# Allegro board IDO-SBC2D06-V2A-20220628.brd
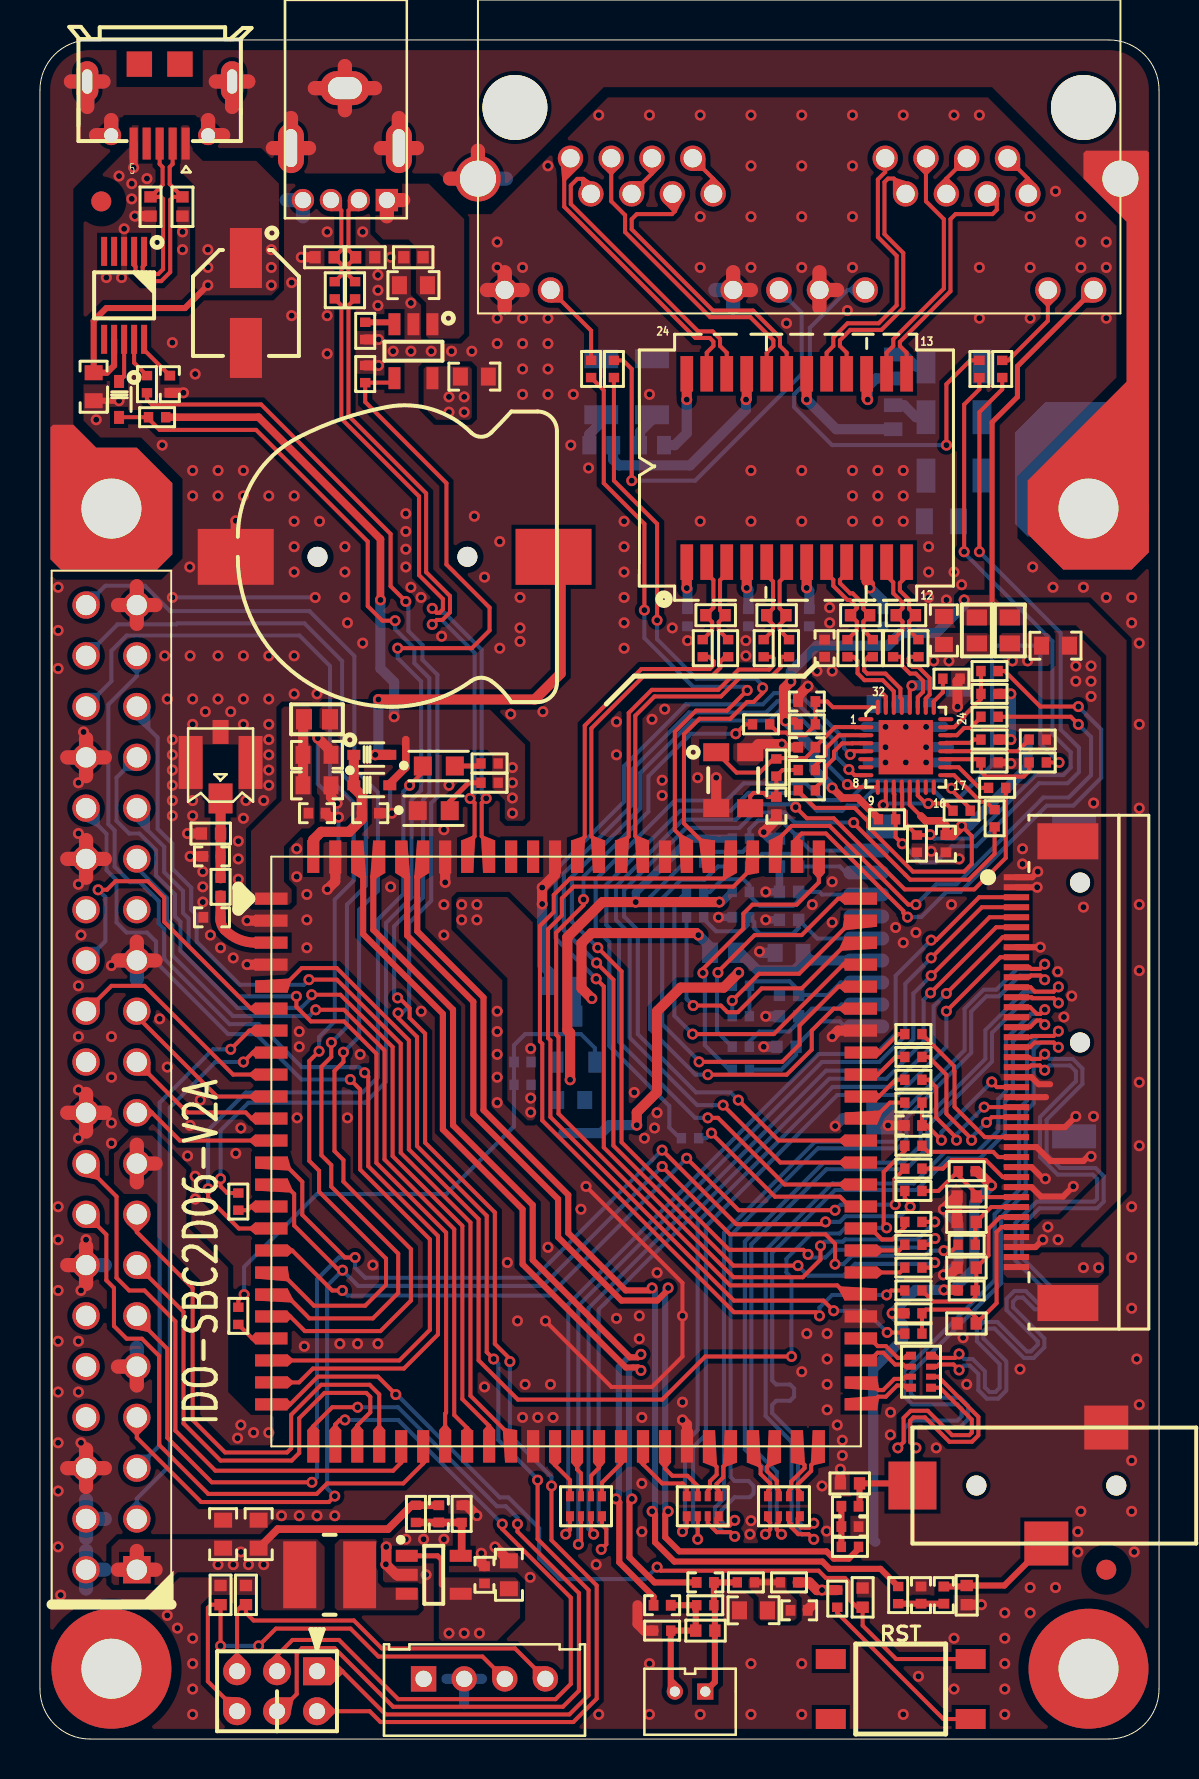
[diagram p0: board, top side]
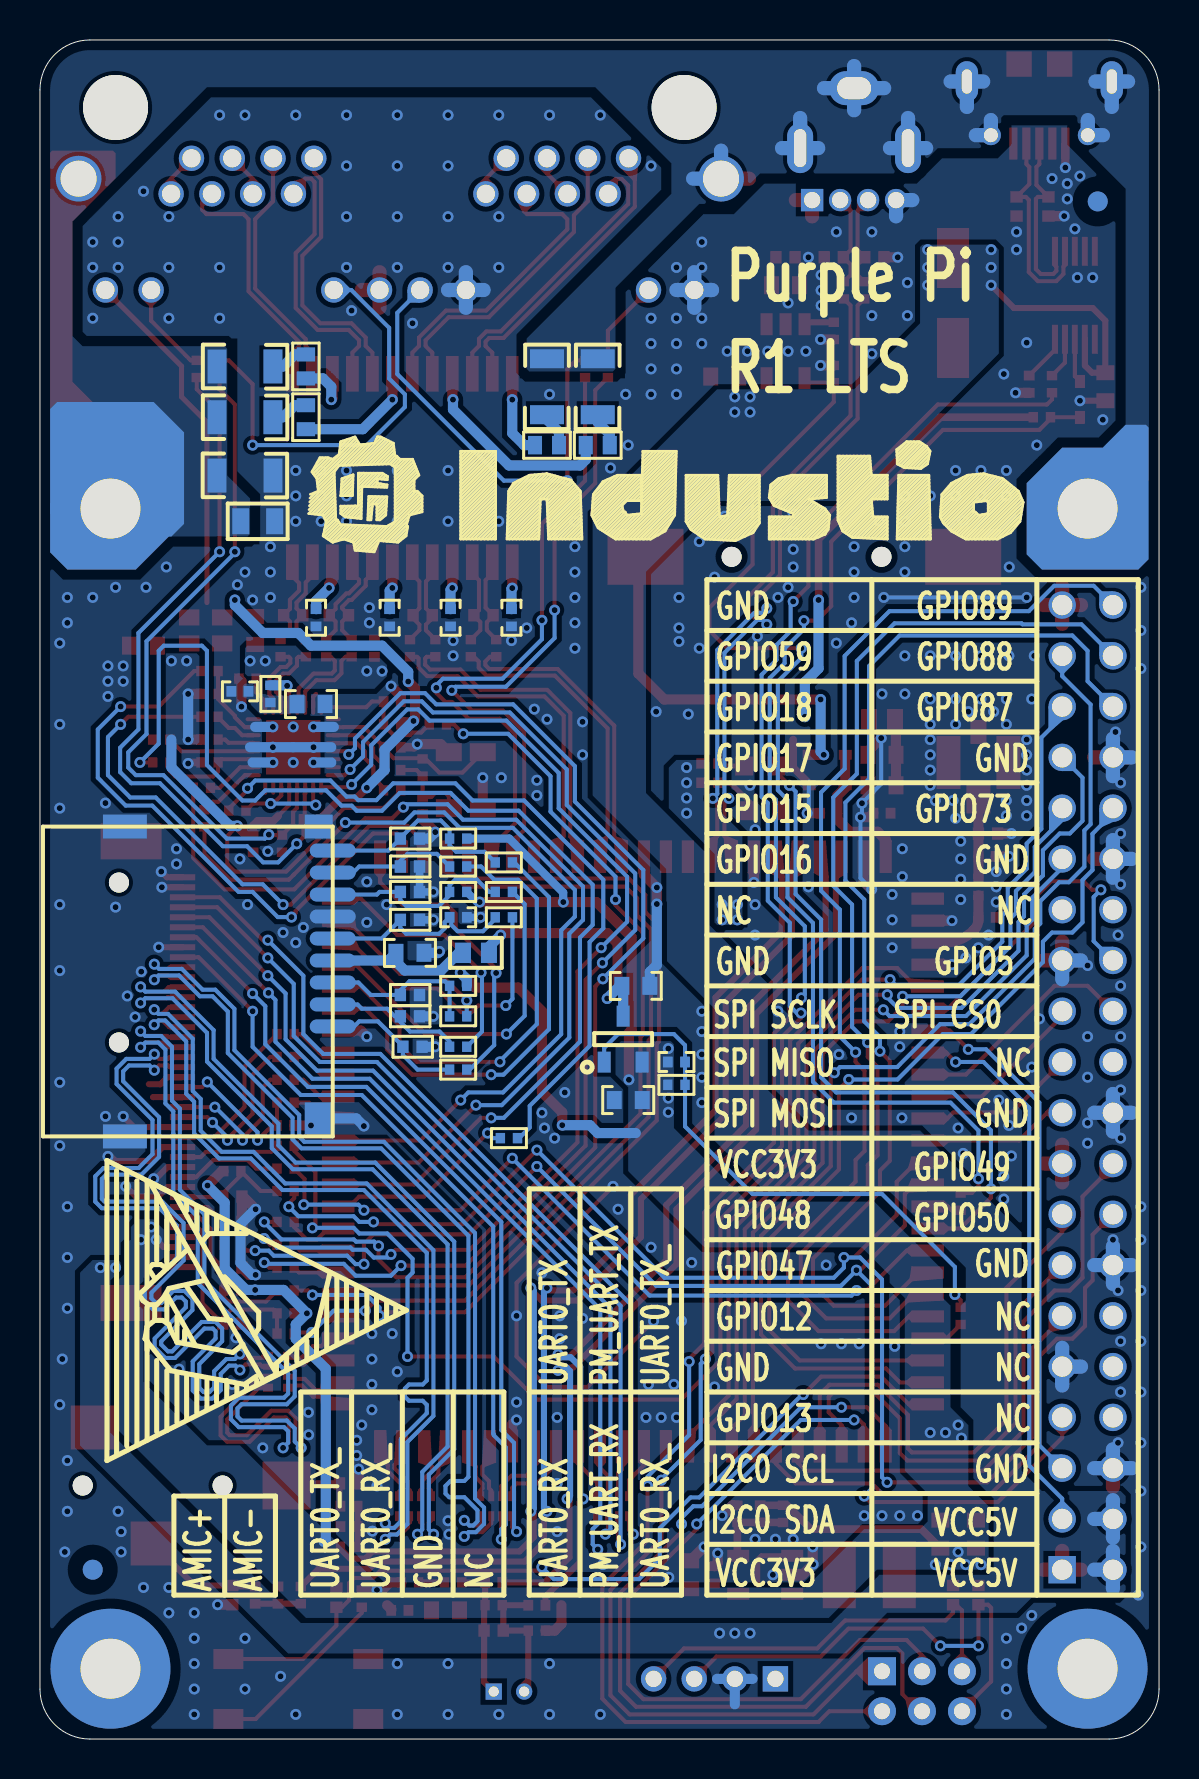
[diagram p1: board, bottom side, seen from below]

Outline 56 x 85 mm; copper layers: TOP, BOTTOM. Coordinates in mm from the lower left corner of the outline.
Outline path: 0,82.5 arc(0.73,84.27) 2.5,85 53.5,85 arc(55.27,84.27) 56,82.5 56,2.5 arc(55.27,0.73) 53.5,0 2.5,0 arc(0.73,0.73) 0,2.5 0,82.5

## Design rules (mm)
net group PANEL_DE: nets PANEL_DE TTL27/LCD_DE
net group PANEL_HS: nets PANEL_HS TTL25/LCD_HSYNC
net group PANEL_VS: nets PANEL_VS TTL26/LCD_VSYNC
net group CLK: nets 50MHZ_CLKOUT DMIC_CLK DMIC_L DMIC_R GPIO1/RMII_MDC PANEL_DCLK RMII_MDC RMII_REF_CLK TTL20 TTL24/LCD_PCLK
net group LAN: nets ETH_RN ETH_RP ETH_RXN ETH_RXP ETH_TN ETH_TP ETH_TXN ETH_TXP LAN0-R+ LAN0-R- LAN0-T+ LAN0-T- LAN1-R+ LAN1-R- LAN1-T+ LAN1-T- MDI_RN MDI_RP MDI_RXN MDI_RXP MDI_TN MDI_TP MDI_TXN MDI_TXP PANEL_B3 PANEL_B4 PANEL_B5 PANEL_B6 PANEL_B7 PANEL_G2 PANEL_G3 PANEL_G4 PANEL_G5 PANEL_G6 PANEL_G7 PANEL_R3 PANEL_R4 PANEL_R5 PANEL_R6 PANEL_R7 TTL0 TTL1 TTL2 TTL3 TTL4 TTL5 TTL6/MIPI_TX_D0P TTL7/MIPI_TX_D0N TTL8/MIPI_TX_D1P TTL9/MIPI_TX_D1N TTL10/MIPI_TX_CKP TTL11/MIPI_TX_CKN TTL12/MIPI_TX_D2P TTL13/MIPI_TX_D2N TTL14/MIPI_TX_D3P TTL15/MIPI_TX_D3N
net group PHY_DVDD33: nets RMII_MDIO
net group SD: nets SD_CDZ SD_CLK SD_CLK_ SD_CMD SD_CMD_ SD_D0 SD_D0_ SD_D1 SD_D1_ SD_D2 SD_D2_ SD_D3 SD_D3_
net group USB: nets DM_P1 DM_P2 DM_P2_ DP_P1 DP_P2 DP_P2_ UD+ UD-

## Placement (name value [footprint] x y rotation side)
C1  100uF/10V  [CAPAE530X540]  10.31 71.84 270 top
C2  10uF  [C0603L]  23.46 8.22 270 top
C3  1uF  [C0402L]  22.25 8.22 270 top
C4  6.8pF  [C0402L]  19.96 11.26 90 top
C5  22uF  [C0603L]  10.94 10.25 270 top
C6  22uF  [C0603L]  9.16 10.25 270 top
C7  1uF  [C0402L]  16.53 46.32 180 top
C8  100nF  [C0402L]  13.86 46.32 180 top
C9  22uF  [C0603L]  13.86 49.24 180 top
C10  22uF  [C0603L]  13.86 47.71 180 top
C11  NC/10pF  [C0402L]  8.61 41.11 0 top
C12  NC/10pF  [C0402L]  8.61 44.16 0 top
C13  10uF  [C0603L]  37.49 39.33 0 bottom
C14  NC/6.8pF  [C0402L]  35.07 41.11 0 bottom
C15  10uF  [C0603L]  26.56 31.97 180 bottom
C16  1uF  [C0402L]  24.15 33.87 0 bottom
C17  10uF  [C0603L]  26.18 37.68 0 bottom
C18  10uF  [C0603L]  18.69 72.73 0 top
C19  10uF  [C0603L]  21.74 68.16 180 top
C20  100nF  [C0402L]  32.41 56.1 270 bottom
C21  1nF  [C1206L]  30.63 67.65 270 bottom
C22  100nF  [C0402L]  35.45 56.1 270 bottom
C23  1nF  [C1206L]  28.09 67.65 270 bottom
C24  100nF  [C0402L]  38.5 56.1 270 bottom
C25  1nF  [C1206L]  45.74 66.13 180 bottom
C26  100nF  [C0402L]  42.18 56.1 270 bottom
C27  1nF  [C1206L]  45.74 68.67 180 bottom
C28  1nF  [C1206L]  45.74 63.21 0 bottom
C29  100nF  [C0402L]  45.99 52.41 180 bottom
C30  10uF  [C0603L]  42.44 51.78 0 bottom
C31  10uF  [C0603L]  50.82 54.7 180 top
C32  100nF  [C0402L]  45.33 44.79 90 top
C33  10uF  [C0603L]  45.23 55.46 270 top
C34  100nF  [C0402L]  39.26 54.57 270 top
C35  18pF  [C0402L]  38.37 49.62 0 top
C36  100nF  [C0402L]  38.37 51.9 0 top
C37  18pF  [C0402L]  36.85 46.7 90 top
C38  NC/6.8pF  [C0402L]  43.71 30.7 0 top
C39  4.7uF  [C0402L]  40.53 11.65 180 top
C40  4.7uF  [C0402L]  45.23 7.2 270 top
C41  NC/4.7uF  [C0402L]  44.09 7.2 270 top
C42  NC/4.7uF  [C0402L]  40.53 10.63 180 top
C43  10uF  [C0603L]  35.71 6.44 0 top
C44  100nF  [C0402L]  37.99 6.44 180 top
C45  1uF  [C0402L]  33.29 7.84 180 top
C46  1uF  [C0402L]  31.14 6.69 180 top
C47  10uF  [C0603L]  2.69 67.65 90 top
C48  100nF  [C0402L]  6.5 67.78 90 top
D1  ES0402V014CT  [V0402]  7.13 76.67 270 top
D2  ES0402V014CT  [V0402]  5.53 76.67 270 top
D3  ES0402V014CT  [V0402]  41.17 7.07 90 top
D4  LRB520S-30T1G  [SOD523]  16.61 47.71 0 top
D5  LRB520S-30T1G  [SOD523]  16.61 49.24 0 top
D6  ES0402V014CT  [V0402]  8.56 45.3 180 top
D7  ES0402V014CT  [V0402]  37.49 42.38 180 bottom
D8  ES0402V014CT  [V0402]  37.49 43.65 180 bottom
D9  ES0402V014CT  [V0402]  37.36 34.63 180 bottom
D10  ES0402V014CT  [V0402]  37.49 36.16 180 bottom
D11  ES0402V014CT  [V0402]  37.49 37.22 180 bottom
D12  ES0402V014CT  [V0402]  37.49 45.05 180 bottom
D13  ES0402V014CT  [V0402]  37.49 40.98 180 bottom
D14  ES0402V014CT  [V0402]  14.24 74.13 180 top
D15  ES0402V014CT  [V0402]  16.28 74.13 0 top
D16  ES0402V014CT  [V0402]  18.69 74.13 180 top
D17  ES0402V014CT  [V0402]  33.8 56.22 0 top
D18  ES0402V014CT  [V0402]  36.85 56.22 0 top
D19  ES0402V014CT  [V0402]  41.04 56.22 0 top
D20  ES0402V014CT  [V0402]  43.33 56.22 0 top
D21  ES0402V014CT  [V0402]  46.38 25.87 180 top
D22  ES0402V014CT  [V0402]  46.38 27.14 180 top
D23  ES0402V014CT  [V0402]  46.38 20.79 180 top
D24  ES0402V014CT  [V0402]  46.38 23.58 180 top
D25  ES0402V014CT  [V0402]  46.38 7.2 270 top
D26  ES0402V014CT  [V0402]  40.53 12.79 180 top
D27  NC/ES0402V014CT  [V0402]  33.29 5.42 0 top
D28  ES0402V014CT  [V0402]  10.31 7.2 90 top
D29  ES0402V014CT  [V0402]  9.04 7.2 90 top
D30  LRB520S-30T1G  [SOD523]  3.96 67.02 270 top
H1  HOLE  [MTG300_600]  52.47 3.52 0 top
H2  HOLE  [MTG300_600]  52.47 61.56 0 top
H3  HOLE  [MTG300_600]  3.58 61.56 0 top
H4  HOLE  [MTG300_600]  3.58 3.52 0 top
J1  MicroUSB  [MICROUSB-5SB]  5.99 79.72 0 top
J2  -  [CR1220-2P-SMD]  9.8 59.14 0 top
J3  IPEX  [IPEX-20279-001E]  9.04 48.86 270 top
J4  SD  [TF-01A]  41.55 35.65 270 bottom
J5  USB-4AF  [USB-4AF-DIP-3W]  15.26 79.59 180 top
J6  RJ45  [RJ45-1X2-8P8C-R-LED]  45.87 81.62 180 top
J7  -  [FPC05-PDW-40P]  50.44 33.36 90 top
J8  PJ-326-3P  [PJ-326A-3P]  53.36 15.58 180 top
J9  MX1.25T-2A  [MX125T-2A]  33.29 2.37 0 top
J10  PH2.0-4A  [PH200-4A]  25.29 3.01 180 top
J11  -  [HDR200MA-2X3]  13.86 3.39 180 top
J12  -  [HDR254MA-2X20]  4.08 31.33 180 top
L1  2.2uH/4.3A  [L4040]  14.5 8.22 180 top
L2  UPZ1608E101-3R0TF  [L0603]  13.86 51.02 180 top
L3  UPZ1608E101-3R0TF  [L0603]  34.18 39.33 0 bottom
L4  UPZ1608E101-3R0TF  [L0603]  48.53 55.46 270 top
L5  UPZ1608E101-3R0TF  [L0603]  46.88 55.46 270 top
LED1  Blue LED0603  [LED0603]  19.96 48.68 0 top
LED2  Blue LED0603  [LED0603]  19.71 46.44 0 top
MARK1  FID10X20  [MARK]  53.36 8.47 0 top
MARK2  FID10X20  [MARK]  3.07 76.92 180 bottom
MARK3  FID10X20  [MARK]  53.36 8.47 180 bottom
MARK4  FID10X20  [MARK]  3.07 76.92 0 top
Q1  CJ3401  [SOT23]  26.82 35.01 90 bottom
R1  4.7K  [R0402L]  39.9 7.02 270 top
R2  1K  [R0402L]  22.5 48.81 180 top
R3  200K  [R0402L]  18.82 11.26 270 top
R4  1K  [R0402L]  22.5 47.84 180 top
R5  44.2K  [R0402L]  21.1 11.26 90 top
R6  0R  [R0402L]  9.04 42.63 90 top
R7  10K  [R0402L]  35.07 42.38 0 bottom
R8  10K  [R0402L]  35.07 37.68 0 bottom
R9  10K  [R0402L]  35.07 45.05 0 bottom
R10  22R  [R0402L]  32.79 42.38 0 bottom
R11  22R  [R0402L]  35.07 43.65 0 bottom
R12  0R  [R0402L]  15.77 72.48 90 top
R13  22R  [R0402L]  35.07 33.49 0 bottom
R14  0R  [R0402L]  14.75 72.48 90 top
R15  22R  [R0402L]  35.07 34.63 0 bottom
R16  22R  [R0402L]  35.07 36.16 0 bottom
R17  22R  [R0402L]  32.79 43.85 0 bottom
R18  22R  [R0402L]  32.79 41.11 0 bottom
R19  22R  [R0402L]  9.93 26.89 90 top
R20  100K  [R0402L]  24.15 32.73 180 bottom
R21  10K  [R0402L]  9.93 21.17 90 top
R22  6.8K  [R0402L]  16.28 70.45 270 top
R23  2.2R  [R0402L]  33.17 54.57 90 top
R24  75R  [R0603L]  30.63 64.73 180 bottom
R25  2.2R  [R0402L]  34.44 54.57 90 top
R26  2.2R  [R0402L]  36.22 54.57 90 top
R27  2.2R  [R0402L]  37.49 54.57 90 top
R28  75R  [R0603L]  28.09 64.73 180 bottom
R29  1K  [R0402L]  27.58 68.54 90 top
R30  2.2R  [R0402L]  40.41 54.57 90 top
R31  1K  [R0402L]  28.72 68.54 90 top
R32  75R  [R0603L]  42.69 66.13 90 bottom
R33  2.2R  [R0402L]  41.68 54.57 90 top
R34  2.2R  [R0402L]  42.69 54.57 90 top
R35  75R  [R0603L]  42.69 68.67 90 bottom
R36  1K  [R0402L]  47.01 68.54 270 top
R37  2.2R  [R0402L]  43.96 54.57 90 top
R38  1K  [R0402L]  48.15 68.54 270 top
R39  1M  [R0805L]  45.11 60.92 0 bottom
R40  22R  [R0402L]  47.52 53.43 180 top
R41  22R  [R0402L]  47.52 51.14 180 top
R42  0R  [R0402L]  44.47 52.29 270 bottom
R43  22R  [R0402L]  49.93 48.86 180 top
R44  22R  [R0402L]  47.9 47.59 180 top
R45  22R  [R0402L]  47.77 46.06 90 top
R46  6.19K  [R0402L]  45.61 53.05 0 top
R47  22R  [R0402L]  32.53 30.06 180 bottom
R48  22R  [R0402L]  43.71 24.73 0 top
R49  22R  [R0402L]  43.71 23.58 0 top
R50  22R  [R0402L]  43.71 25.87 0 top
R51  22R  [R0402L]  36.09 50.76 0 top
R52  0R  [R0402L]  46.12 46.44 180 top
R53  1M  [R0402L]  36.85 48.6 270 top
R54  0R  [R0402L]  38.37 48.48 0 top
R55  4.7K  [R0402L]  38.37 47.46 0 top
R56  4.7K  [R0402L]  49.93 50 180 top
R57  470K  [R0402L]  38.37 50.76 0 top
R58  4.7K  [R0402L]  47.52 48.86 180 top
R59  4.7K  [R0402L]  47.52 50 180 top
R60  4.7K  [R0402L]  47.52 52.29 180 top
R61  4.7K  [R0402L]  42.39 46.01 0 top
R62  4.7K  [R0402L]  43.89 44.79 270 top
R63  22R  [RN_0402X4]  27.33 11.65 270 top
R64  22R  [RN_0402X4]  37.23 11.65 270 top
R65  22R  [RN_0402X4]  33.17 11.65 270 top
R66  22R  [RN_0402X4]  44.09 18.38 0 top
R67  22R  [R0402L]  43.71 32.98 0 top
R68  22R  [R0402L]  43.71 34.12 0 top
R69  22R  [R0402L]  43.71 35.27 0 top
R70  22R  [R0402L]  43.71 29.68 0 top
R71  22R  [R0402L]  43.71 28.54 0 top
R72  22R  [R0402L]  43.71 31.84 0 top
R73  NC/4.7K  [R0402L]  46.38 28.41 180 top
R74  4.7K  [R0402L]  43.71 21.3 0 top
R75  4.7K  [R0402L]  46.38 22.44 0 top
R76  22R  [R0402L]  43.71 22.44 0 top
R77  22R  [R0402L]  43.71 20.28 0 top
R78  22R  [R0402L]  46.38 24.73 0 top
R79  22R  [R0402L]  43.71 27.42 0 top
R80  0R  [R0402L]  40.53 9.61 180 top
R81  0R  [R0402L]  42.95 7.2 270 top
R82  4.7K  [R0402L]  37.49 7.84 180 top
R83  2K  [R0402L]  35.33 7.84 180 top
R84  NC/2K  [R0402L]  33.29 6.69 180 top
R85  2K  [R0402L]  31.14 5.42 180 top
R88  22R  [R0402L]  5.35 67.78 90 top
R89  10K  [R0402L]  5.86 66.13 180 top
R123  510K  [R0402L]  16.28 68.29 90 top
SW1  T-switch  [PB-4P-S-4_5X4_5]  43.07 2.5 180 top
U1  TLV62569DBVR  [SOT23-5]  19.71 8.22 0 top
U2  U-2D01  [IDO_2D01_LGA96]  11.58 43.14 0 top
U3  SY6280AAC  [SOT23-5]  18.69 69.43 270 top
U4  QT24A01  [QT24A01-SOP24]  37.87 63.59 270 top
U5  IP101GR  [IP101GR-VQFN-32]  43.33 49.62 0 top
U6  CH340E  [MSOP-10]  4.21 72.22 270 top
XT1  25MHz  [XTAL_32X25_4P]  34.69 47.97 0 top

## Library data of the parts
C1 = C-AL-SMD
C2 C5 C6 C9 C10 C13 C15 C17-C19 C30 C31 C33 C43 C47 = C-0603
C3 C4 C7 C8 C11 C12 C14 C16 C20 C22 C24 C26 C29 C32 C34-C42 C44-C46 C48 = C-0402
C21 C23 C25 C27 C28 = C-1206
D1-D3 D6-D29 = DI-ESD
D4 D5 D30 = DI-XI-S
H1-H4 = HOLE: User Part Number: pn; Tolerance: RichardLC
J1 = J-MicroUSB_0
J2 = RTC-CR1220-2P-SMD
J3 = RF-IPEX-20279
J4 = J-TF-01A
J5 = J-USB-4AF-DIP-W-3_1
J6 = J-RJ45-1X2
J7 = J-FPC05-40P: User Part Number: DENG
J8 = J-PJ-326A-3P
J9 = J-H-2P
J10 = J-H-4P
J11 = J-HDR-D-6: User Part Number: pn; Tolerance: RichardLC
J12 = J-HDR-D-40
L1 = L-IND
L2 L4 L5 = FB-0603
L3 = FB-0603: signal model: CM-LITE_0_CMLS-ACM2012_ACM201_1_ACM2012-900-2P_NC
LED1 LED2 = D-LED0603
MARK1-MARK4 = MTG240_600_NPH_0
Q1 = P-MOS
R1-R23 R25-R27 R29-R31 R33 R34 R36-R38 R40-R59 R70-R85 R88 R89 R123 = R-0402
R24 R28 R32 R35 = R-0603
R39 = R-0805
R60-R62 = R-0402: signal model: R_R0402_33R_33R
R63-R66 = RN_0402X4
R67-R69 = R-0402: signal model: R_R0402_10K_10K
SW1 = SW-TS4550TP
U1 = U-TLV62569DBVR
U2 = U-2D01_1
U3 = U-SY6280AAC
U4 = U-QT24A01_0
U5 = U-IP101GR
U6 = U-CH340E_0
XT1 = XTAL-4P

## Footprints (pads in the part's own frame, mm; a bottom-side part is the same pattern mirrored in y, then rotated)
C0402L
  rect 0.49x0.54 smd: 1(-0.43,0) 2(0.43,0)
C0603L
  rect 0.75x0.9 smd: 1(-0.7,0) 2(0.7,0)
C1206L
  rect 0.95x1.7 smd: 1(-1.4,0) 2(1.4,0)
CAPAE530X540
  rect 3x1.6 smd: 1(-2.25,0) 2(2.25,0)
CR1220-2P-SMD
  round 1.001 hole 1.199 unplated: (4.089,0) (11.59,0)
  rect 3.8x2.799 smd: 1(15.9,0) 2(0,0)
FPC05-PDW-40P
  rect 0.305x1.27 smd: 1(9.751,1.575) 2(9.251,1.575) 3(8.75,1.575) 4(8.25,1.575) 5(7.749,1.575) 6(7.249,1.575) 7(6.749,1.575) 8(6.251,1.575) 9(5.751,1.575) 10(5.25,1.575) 11(4.75,1.575) 12(4.249,1.575) 13(3.749,1.575) 14(3.251,1.575) 15(2.751,1.575) 16(2.25,1.575) 17(1.75,1.575) 18(1.25,1.575) 19(0.749,1.575) 20(0.249,1.575) 21(-0.249,1.575) 22(-0.749,1.575) 23(-1.25,1.575) 24(-1.75,1.575) 25(-2.25,1.575) 26(-2.751,1.575) 27(-3.251,1.575) 28(-3.749,1.575) 29(-4.249,1.575) 30(-4.75,1.575) 31(-5.25,1.575) 32(-5.751,1.575) 33(-6.251,1.575) 34(-6.749,1.575) 35(-7.249,1.575) 36(-7.749,1.575) 37(-8.25,1.575) 38(-8.75,1.575) 39(-9.251,1.575) 40(-9.751,1.575)
  rect 1.803x3.048 smd: 41(11.549,-1.001) 42(-11.549,-1.001)
HDR200MA-2X3
  rect 1.4x1.4 hole 0.8: 1(0,0)
  round 1.4 hole 0.8: 2(0,2) 3(2,0) 4(2,2) 5(4,0) 6(4,2)
HDR254MA-2X20
  rect 1.372x1.372 hole 1.016: 1(-0.762,22.86)
  round 1.372 hole 1.016: 2(1.778,22.86) 3(-0.762,20.32) 4(1.778,20.32) 5(-0.762,17.78) 6(1.778,17.78) 7(-0.762,15.24) 8(1.778,15.24) 9(-0.762,12.7) 10(1.778,12.7) 11(-0.762,10.16) 12(1.778,10.16) 13(-0.762,7.62) 14(1.778,7.62) 15(-0.762,5.08) 16(1.778,5.08) 17(-0.762,2.54) 18(1.778,2.54) 19(-0.762,0) 20(1.778,0) 21(-0.762,-2.54) 22(1.778,-2.54) 23(-0.762,-5.08) 24(1.778,-5.08) 25(-0.762,-7.62) 26(1.778,-7.62) 27(-0.762,-10.16) 28(1.778,-10.16) 29(-0.762,-12.7) 30(1.778,-12.7) 31(-0.762,-15.24) 32(1.778,-15.24) 33(-0.762,-17.78) 34(1.778,-17.78) 35(-0.762,-20.32) 36(1.778,-20.32) 37(-0.762,-22.86) 38(1.778,-22.86) 39(-0.762,-25.4) 40(1.778,-25.4)
IDO_2D01_LGA96
  rect 1.626x0.61 smd: 1(0,-1.1) 2(0,-2.2) 3(0,-3.3) 4(0,-4.4) 5(0,-5.5) 6(0,-6.6) 7(0,-7.7) 8(0,-8.8) 9(0,-9.9) 10(0,-11) 11(0,-12.1) 12(0,-13.2) 13(0,-14.3) 14(0,-15.4) 15(0,-16.5) 16(0,-17.6) 17(0,-18.7) 18(0,-19.8) 19(0,-20.9) 20(0,-22) 21(0,-23.1) 22(0,-24.2) 23(0,-25.3) 24(0,-26.4) 49(29.5,-26.4) 50(29.5,-25.3) 51(29.5,-24.2) 52(29.5,-23.1) 53(29.5,-22) 54(29.5,-20.9) 55(29.5,-19.8) 56(29.5,-18.7) 57(29.5,-17.6) 58(29.5,-16.5) 59(29.5,-15.4) 60(29.5,-14.3) 61(29.5,-13.2) 62(29.5,-12.1) 63(29.5,-11) 64(29.5,-9.9) 65(29.5,-8.8) 66(29.5,-7.7) 67(29.5,-6.6) 68(29.5,-5.5) 69(29.5,-4.4) 70(29.5,-3.3) 71(29.5,-2.2) 72(29.5,-1.1)
  rect 0.61x1.626 smd: 25(2.1,-28.5) 26(3.2,-28.5) 27(4.3,-28.5) 28(5.4,-28.5) 29(6.5,-28.5) 30(7.6,-28.5) 31(8.7,-28.5) 32(9.8,-28.5) 33(10.9,-28.5) 34(12,-28.5) 35(13.1,-28.5) 36(14.2,-28.5) 37(15.3,-28.5) 38(16.4,-28.5) 39(17.5,-28.5) 40(18.6,-28.5) 41(19.7,-28.5) 42(20.8,-28.5) 43(21.9,-28.5) 44(23,-28.5) 45(24.1,-28.5) 46(25.2,-28.5) 47(26.3,-28.5) 48(27.4,-28.5) 73(27.4,1) 74(26.3,1) 75(25.2,1) 76(24.1,1) 77(23,1) 78(21.9,1) 79(20.8,1) 80(19.7,1) 81(18.6,1) 82(17.5,1) 83(16.4,1) 84(15.3,1) 85(14.2,1) 86(13.1,1) 87(12,1) 88(10.9,1) 89(9.8,1) 90(8.7,1) 91(7.6,1) 92(6.5,1) 93(5.4,1) 94(4.3,1) 95(3.2,1) 96(2.1,1)
IP101GR-VQFN-32
  oval 0.762x0.203 smd: 1(-2,1.4) 2(-2,1) 3(-2,0.6) 4(-2,0.2) 5(-2,-0.2) 6(-2,-0.6) 7(-2,-1) 8(-2,-1.4) 17(2,-1.4) 18(2,-1) 19(2,-0.6) 20(2,-0.2) 21(2,0.2) 22(2,0.6) 23(2,1) 24(2,1.4)
  oval 0.203x0.762 smd: 9(-1.4,-2) 10(-1,-2) 11(-0.6,-2) 12(-0.2,-2) 13(0.2,-2) 14(0.6,-2) 15(1,-2) 16(1.4,-2) 25(1.4,2) 26(1,2) 27(0.6,2) 28(0.2,2) 29(-0.2,2) 30(-0.6,2) 31(-1,2) 32(-1.4,2)
  rect 2.718x2.718 smd: 33(0,0)
IPEX-20279-001E
  rect 1.2x0.8 smd: 1(-1.525,0)
  rect 1.5x1.2 smd: 2(1.8,0)
  rect 2.65x1.2 smd: 3(0,-1.5) 4(0,1.5)
L0603
  rect 0.8x1.02 smd: 1(-0.65,0) 2(0.65,0)
L4040
  rect 1.65x3.35 smd: 1(-1.5,0) 2(1.5,0)
LED0603
  rect 0.9x0.95 smd: A(0.8,0) C(-0.8,0)
MARK
  round 1 smd: 1(0,0)
MICROUSB-5SB
  rect 1.27x1.27 smd: (-1.016,4.075) (1.016,4.075)
  rect 0.406x1.6 smd: 1(1.301,0.1) 2(0.65,0.1) 3(0,0.1) 4(-0.65,0.1) 5(-1.301,0.1)
  oval 1.118x2.032 hole 0.508x1.219: 6(3.625,3.205) 7(-3.625,3.205)
  round 1 hole 0.7: 8(-2.425,0.52) 9(2.425,0.52)
MSOP-10
  rect 1.45x0.3 smd: 1(-2.2,1) 2(-2.2,0.5) 3(-2.2,0) 4(-2.2,-0.5) 5(-2.2,-1) 6(2.2,-1) 7(2.2,-0.5) 8(2.2,0) 9(2.2,0.5) 10(2.2,1)
MTG300_600
  round 6 hole 3: 1(0,0)
MX125T-2A
  rect 0.813x0.813 hole 0.508: 1(0,0)
  round 0.813 hole 0.508: 2(-1.524,0)
PB-4P-S-4_5X4_5
  rect 1.5x1 smd: 1(-3.5,1.5) 2(3.5,1.5) 3(-3.5,-1.5) 4(3.5,-1.5)
PH200-4A
  rect 1.27x1.27 hole 0.813: 1(6.096,0)
  round 1.27 hole 0.813: 2(4.064,0) 3(2.032,0) 4(0,0)
PJ-326A-3P
  round 1 hole 1: (-0.5,2.901) (6.5,2.901)
  rect 2.2x2.2 smd: 1(0,0) 2(3,5.801)
  rect 2.4x2.4 smd: 3(9.7,2.901)
QT24A01-SOP24
  rect 1.778x0.635 smd: 1(4.71,-5.5) 2(4.71,-4.5) 3(4.71,-3.5) 4(4.71,-2.5) 5(4.71,-1.5) 6(4.71,-0.5) 7(4.71,0.5) 8(4.71,1.5) 9(4.71,2.5) 10(4.71,3.5) 11(4.71,4.5) 12(4.71,5.5) 13(-4.71,5.5) 14(-4.71,4.5) 15(-4.71,3.5) 16(-4.71,2.5) 17(-4.71,1.5) 18(-4.71,0.5) 19(-4.71,-0.5) 20(-4.71,-1.5) 21(-4.71,-2.5) 22(-4.71,-3.5) 23(-4.71,-4.5) 24(-4.71,-5.5)
R0402L
  rect 0.47x0.52 smd: 1(-0.43,0) 2(0.43,0)
R0603L
  rect 0.7x0.92 smd: 1(-0.6,0) 2(0.6,0)
R0805L
  rect 0.85x1.3 smd: 1(-0.85,0) 2(0.85,0)
RJ45-1X2-8P8C-R-LED
  round 3.25 hole 3.25 unplated: (-6.35,0) (22.1,0)
  round 1.27 hole 0.914: A1(3.57,2.54) A2(2.55,4.32) A3(1.53,2.54) A4(0.51,4.32) A5(-0.51,2.54) A6(-1.53,4.32) A7(-2.55,2.54) A8(-3.57,4.32) A9(6.86,9.13) A10(4.57,9.13) A11(-4.57,9.13) A12(-6.86,9.13) B1(19.32,2.54) B2(18.3,4.32) B3(17.28,2.54) B4(16.26,4.32) B5(15.24,2.54) B6(14.22,4.32) B7(13.2,2.54) B8(12.18,4.32) B9(22.61,9.13) B10(20.32,9.13) B11(11.18,9.13) B12(8.89,9.13)
  round 2.286 hole 1.803: FG1(-8.2,3.56) FG2(23.95,3.56)
RN_0402X4
  rect 0.5x0.4 smd: 1(-0.5,0.8) 4(-0.5,-0.8) 5(0.5,-0.8) 8(0.5,0.8)
  rect 0.5x0.3 smd: 2(-0.5,0.25) 3(-0.5,-0.25) 6(0.5,-0.25) 7(0.5,0.25)
SOD523
  rect 0.65x0.5 smd: A(0.9,0) C(-0.9,0)
SOT23
  rect 1.05x0.65 smd: 1(-1.15,0.95) 2(-1.15,-0.95) 3(1.15,0)
SOT23-5
  rect 1.1x0.6 smd: 1(-1.35,0.95) 2(-1.35,0) 3(-1.35,-0.95) 4(1.35,-0.95) 5(1.35,0.95)
TF-01A
  round 1 hole 1: (-7.2,-10.5) (0.8,-10.5)
  oval 0.7x2.3 smd: 1(0,0.2) 2(-1.1,0.2) 3(-2.2,0.2) 4(-3.3,0.2) 5(-4.4,0.2) 6(-5.5,0.2) 7(-6.6,0.2) 8(-7.7,0.2) 9(-8.8,0.2)
  rect 1.2x1.4 smd: 10(-10,-0.5)
  rect 1.6x1.4 smd: 11(4.6,-0.5)
  rect 1.2x2.2 smd: 12(-10,-10.2) 13(5.5,-10.2)
USB-4AF-DIP-3W
  rect 1.118x1.118 hole 0.813: 1(-2.1,2.6)
  round 1.118 hole 0.813: 2(-0.7,2.6) 3(0.7,2.6) 4(2.1,2.6)
  oval 1.3x2.5 hole 0.62x1.9: 5(-2.7,0) 6(2.7,0)
  oval 2.5x1.7 hole 1.7x1.1: 7(0,-3)
V0402
  rect 0.57x0.62 smd: 1(-0.48,0) 2(0.48,0)
XTAL_32X25_4P
  rect 1.3x0.9 smd: 1(-0.85,1.4) 2(-0.85,-1.4) 3(0.85,-1.4) 4(0.85,1.4)

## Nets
GND: C1.2 C2.1 C3.1 C5.1 C6.1 C7.1 C8.1 C9.1 C10.1 C11.1 C12.1 C13.1 C14.1 C15.1 C17.1 C18.1 C19.1 C20.2 C22.2 C24.2 C26.2 C28.1 C29.1 C30.1 C31.1 C32.1 C33.1 C34.1 C35.1 C36.1 C37.1 C38.1 C41.1 C42.1 C43.1 C44.1 C47.1 C48.1 D1.2(I/O1) D2.2(I/O1) D3.2(I/O1) D6.2(I/O1) D7.2(I/O1) D8.2(I/O1) D9.2(I/O1) D10.2(I/O1) D11.2(I/O1) D12.2(I/O1) D13.2(I/O1) D14.2(I/O1) D15.2(I/O1) D16.2(I/O1) D21.2(I/O1) D22.2(I/O1) D23.2(I/O1) D24.2(I/O1) D25.2(I/O1) D26.2(I/O1) D28.2(I/O1) D29.2(I/O1) J1.5(GND) J2.2(-) J3.1(GND1) J3.3(GND2) J3.4(GND3) J4.6(VSS) J4.10(G1) J4.11(G2) J4.12(G3) J4.13(G4) J5.4(GND1) J6.A9(ALEDY-) J6.B9(BLEDY-) J6.B11(BLEDG-) J7.1 J7.2 J7.8 J7.15 J7.21 J7.23 J7.26 J7.28 J7.30 J7.32 J7.41 J7.42 J8.1(COM) J10.2 J12.6 J12.9 J12.14 J12.20 J12.25 J12.30 J12.34 J12.39 LED2.C(CATHODE) R5.2 R22.2 R39.1 R46.2 R56.1 R58.1 R62.2 R85.2 R123.2 U1.2(GND) U2.2(GND1) U2.4(GND2) U2.35(GND3) U2.42(GND4) U2.53(GND5) U2.66(GND6) U2.80(GND7) U2.85(GND8) U2.90(GND9) U2.95(GND10) U3.2(GND) U5.33(EPAD) U6.3(GND) XT1.2 XT1.4
GND_EARTH: C21.1 C23.1 C25.1 C27.1 C28.2 H1.1 H2.1 H3.1 H4.1 J1.6(FG2) J1.7(FG3) J1.8(FG4) J1.9(FG5) J5.5(GND2) J5.6(GND3) J5.7(GND4) J6.FG1 J6.FG2 R39.2
VCC5V: C1.1 C2.2 C3.2 C19.2 C47.2 J1.1(VCC) J7.39 J7.40 J12.2 J12.4 U1.1(EN) U1.4(VIN) U3.5(IN) U6.7(VCC)
VCC_RTC: C7.2 D4.C D5.C U2.96(AVDD_RTC)
50MHZ_CLKOUT: R52.2 U5.10(TXCLK/50MCLKI) U5.14(RXCLK/50M_CLKO)
AUD_LINEOUT_L0: R80.1 U2.92(AUD_LINEOUT_L0)
AUD_LINEOUT_R0: R81.1 U2.91(AUD_LINEOUT_R0)
AUD_MIC+: C45.1 D27.2(I/O1) J9.1 R83.2 R84.1
AUD_MIC-: C46.1 D27.1(I/O2) J9.2 R84.2 R85.1
AUD_MICCM0: C46.2 U2.93(AUD_MICCM0)
AUD_MICIN0: C45.2 U2.94(AUD_MICIN0)
CRS: R56.2 U5.20(CRS/LEDMOD)
DM_P1: U2.86(DM_P1)
DM_P2: R12.1 U2.89(DM_P2)
DM_P2_: D15.1(I/O2) J5.2(D-) R12.2
DMIC_CLK: J12.40 U2.20(DMIC_CLK)
DMIC_L: J12.38 U2.19(DMIC_L)
DMIC_R: J12.36 U2.18(DMIC_R)
DP_P1: U2.87(DP_P1)
DP_P2: R14.1 U2.88(DP_P2)
DP_P2_: D14.1(I/O2) J5.3(D+) R14.2
ET_RX_ER-E: R59.2 U5.21(RXER/INT32)
ETH_RN: R27.1 U2.81(ETH_RN)
ETH_RP: R26.1 U2.82(ETH_RP)
ETH_RXN: D18.2(I/O1) R27.2 U4.6(TD2-)
ETH_RXP: D18.1(I/O2) R26.2 U4.5(TD2+)
ETH_TN: R25.1 U2.83(ETH_TN)
ETH_TP: R23.1 U2.84(ETH_TP)
ETH_TXN: D17.2(I/O1) R25.2 U4.3(TD1-)
ETH_TXP: D17.1(I/O2) R23.2 U4.2(TD1+)
ETH_XI: C35.2 R53.1 U5.2(XI) XT1.1
ETH_XO: R54.2 U5.3(XO)
FUART_CTS: J12.33 U2.33(FUART_CTS)
FUART_RTS: J12.35 U2.34(FUART_RTS)
FUART_RX: J12.31 U2.31(FUART_RX)
FUART_TX: J12.29 U2.32(FUART_TX)
GPIO0/RMII_MDIO: R40.1 U2.74(GPIO0)
GPIO1/RMII_MDC: R41.1 U2.75(GPIO1)
GPIO2/I2C1_SCL: R77.1 U2.76(GPIO2/I2C1_SCL)
GPIO3/I2C1_SDA: R76.1 U2.77(GPIO3/I2C1_SDA)
GPIO4/PWM0: R70.1 U2.5(GPIO4/PWM0)
GPIO5/PWM1: J12.26 U2.6(GPIO5/PWM1)
GPIO6/I2C0_SCL: J12.5 U2.7(GPIO6/I2C0_SCL)
GPIO7/I2C0_SDA: J12.3 U2.8(GPIO7/I2C0_SDA)
GPIO8/UART2_RX/SPI0_CZ: J12.24 U2.9(GPIO8/UART2_RX/SPI0_CZ)
GPIO9/UART2_TX/SPI0_CK: J12.23 U2.10(GPIO9/UART2_TX/SPI0_CK)
GPIO10/SPI0_DI: J12.21 U2.11(GPIO10/SPI0_DI)
GPIO11/SPI0_DO: J12.19 U2.12(GPIO11/SPI0_DO)
GPIO12: J12.11 R79.1 U2.13(GPIO12)
GPIO13: J12.7 R78.1 U2.14(GPIO13)
GPIO14: R19.1 U2.15(GPIO14)
GPIO47: J12.13 U2.27(GPIO47)
GPIO48: J12.15 U2.28(GPIO48)
GPIO85: LED1.C(CATHODE) U2.16(GPIO85)
GPIO86: R71.1 U2.17(GPIO86)
GPIO90: R21.1 U2.21(GPIO90)
INTN: D21.1(I/O2) J7.34 R78.2
LAN0-R+: J6.B3 U4.20(MX2+)
LAN0-R-: J6.B6 U4.19(MX2-)
LAN0-T+: J6.B1 U4.23(MX1+)
LAN0-T-: J6.B2 U4.22(MX1-)
LAN1-R+: J6.A3 U4.14(MX4+)
LAN1-R-: J6.A6 U4.13(MX4-)
LAN1-T+: J6.A1 U4.17(MX3+)
LAN1-T-: J6.A2 U4.16(MX3-)
LCD_PWM: J7.29 R70.2
LCD_RSTB: J7.31 R71.2
LED0/PHYAD0: R38.2 R61.2 U5.11(LED0/PHYAD0)
LED3/PHYAD3: R36.2 R62.1 U5.12(LED3/PHYAD3)
LINEOUTL-: C39.2 C42.2 R80.2
LINEOUTL_: C39.1 D26.1(I/O2) J8.3(R)
LINEOUTR-: C40.2 C41.2 R81.2
LINEOUTR_: C40.1 D25.1(I/O2) J8.2(L)
MDI_RN: R37.1 U5.26(MDIRN)
MDI_RP: R34.1 U5.27(MDIRP)
MDI_RXN: D20.2(I/O1) R37.2 U4.12(TD4-)
MDI_RXP: D20.1(I/O2) R34.2 U4.11(TD4+)
MDI_TN: R33.1 U5.29(MDITN)
MDI_TP: R30.1 U5.30(MDITP)
MDI_TXN: D19.2(I/O1) R33.2 U4.9(TD3-)
MDI_TXP: D19.1(I/O2) R30.2 U4.8(TD3+)
NSD_CD: D12.1(I/O2) J4.9(CD) R9.2 R17.2
PANEL_B3: J7.16 R64.8
PANEL_B4: J7.17 R66.5
PANEL_B5: J7.18 R66.6
PANEL_B6: J7.19 R66.7
PANEL_B7: J7.20 R66.8
PANEL_DCLK: C38.2 J7.22 R72.2
PANEL_DE: J7.27 R69.2
PANEL_G2: J7.9 R65.6
PANEL_G3: J7.10 R65.7
PANEL_G4: J7.11 R65.8
PANEL_G5: J7.12 R64.5
PANEL_G6: J7.13 R64.6
PANEL_G7: J7.14 R64.7
PANEL_HS: J7.24 R67.2
PANEL_R3: J7.3 R63.5
PANEL_R4: J7.4 R63.6
PANEL_R5: J7.5 R63.7
PANEL_R6: J7.6 R63.8
PANEL_R7: J7.7 R65.5
PANEL_VS: J7.25 R68.2
PHY_AVDD33: C33.2 C34.2 L5.2 U5.31(AVD33)
PHY_DVDD33: C31.2 C32.2 L4.2 R55.1 R59.1 R60.1 U5.13(IOVDD)
PM_IRIN: J12.37 U2.23(PM_IRIN)
PM_LED0: R31.1 U2.78(PM_LED0)
PM_LED0_: J6.B12(BLEDG+) R31.2
PM_LED1: R29.1 U2.79(PM_LED1)
PM_LED1_: J6.B10(BLEDY+) R29.2
PM_RESET: D3.1(I/O2) SW1.3 U2.24(PM_RESET)
PM_UART_RX: J11.4 U2.25(PM_UART_RX)
PM_UART_TX: J11.3 U2.26(PM_UART_TX)
REGOUT: R42.1 U5.28(REGOUT)
RMII_COL: R55.2 U5.4(COL/RMII)
RMII_MDC: R41.2 U5.22(MDC)
RMII_MDIO: R40.2 R60.2 U5.23(MDIO)
RMII_REF_CLK: R47.2 R52.1
RMII_RST: C36.2 R51.2 R57.2 U5.32(NRST)
RMII_RX_D0: R44.2 U5.18(RXD0)
RMII_RX_D1: R45.2 U5.17(RXD1)
RMII_RX_DV: R43.2 R58.2 U5.19(RXDV/CRS_DV)
RMII_TX_D0: R48.2 U5.9(TXD0)
RMII_TX_D1: R49.2 U5.8(TXD1)
RMII_TX_EN: R50.2 U5.5(TXEN)
RST#: D22.1(I/O2) J7.33 R73.2 R79.2
RTC_VBAT: D5.A J2.1(+)
SAR_GPIO2: J12.32 U2.22(SAR_GPIO2)
SD_CDZ: R17.1 U2.67(SD_CDZ)
SD_CLK: R18.1 U2.70(SD_CLK)
SD_CLK_: C14.2 D13.1(I/O2) J4.5(CLK) R18.2
SD_CMD: R16.1 U2.71(SD_CMD)
SD_CMD_: D11.1(I/O2) J4.3(CMD) R8.2 R16.2
SD_D0: R10.1 U2.69(SD_D0)
SD_D0_: D7.1(I/O2) J4.7(DATA0) R7.2 R10.2
SD_D1: R11.1 U2.68(SD_D1)
SD_D1_: D8.1(I/O2) J4.8(DATA1) R11.2
SD_D2: R13.1 U2.73(SD_D2)
SD_D2_: D9.1(I/O2) J4.1(DATA2) R13.2
SD_D3: R15.1 U2.72(SD_D3)
SD_D3_: D10.1(I/O2) J4.2(CD/DATA3) R15.2
SOM_3V3: C8.2 C9.2 C10.2 L2.2 U2.1(SYS_3V3)
SYS_3V3: C4.2 C5.2 C6.2 C15.2 C16.2 D4.A J6.A12(ALEDG+) J7.37 J7.38 J12.1 J12.17 L1.2 L2.1 L4.1 L5.1 Q1.2(SOURCE) R1.1 R2.1 R3.1 R4.1 R7.1 R8.1 R9.1 R20.1 R57.1 R61.1 R73.1 R74.1 R75.1 R82.1 R89.1
TF_3V3: C17.2 L3.1 Q1.3(DRAIN)
TP_SCL: D23.1(I/O2) J7.36 R74.2 R77.2
TP_SDA: D24.1(I/O2) J7.35 R75.2 R76.2
TTL0: R63.4 U2.36(TTL0)
TTL1: R63.3 U2.37(TTL1)
TTL2: R63.2 U2.38(TTL2)
TTL3: R63.1 U2.39(TTL3)
TTL4: R65.4 U2.40(TTL4)
TTL5: R65.3 U2.41(TTL5)
TTL6/MIPI_TX_D0P: R65.2 U2.43(TTL6/MIPI_TX_D0P)
TTL7/MIPI_TX_D0N: R65.1 U2.44(TTL7/MIPI_TX_D0N)
TTL8/MIPI_TX_D1P: R64.4 U2.45(TTL8/MIPI_TX_D1P)
TTL9/MIPI_TX_D1N: R64.3 U2.46(TTL9/MIPI_TX_D1N)
TTL10/MIPI_TX_CKP: R64.2 U2.47(TTL10/MIPI_TX_CKP)
TTL11/MIPI_TX_CKN: R64.1 U2.48(TTL11/MIPI_TX_CKN)
TTL12/MIPI_TX_D2P: R66.4 U2.49(TTL12/MIPI_TX_D2P)
TTL13/MIPI_TX_D2N: R66.3 U2.50(TTL13/MIPI_TX_D2N)
TTL14/MIPI_TX_D3P: R66.2 U2.51(TTL14/MIPI_TX_D3P)
TTL15/MIPI_TX_D3N: R66.1 U2.52(TTL15/MIPI_TX_D3N)
TTL16: R51.1 U2.54(TTL16)
TTL17: R49.1 U2.55(TTL17)
TTL18: R48.1 U2.56(TTL18)
TTL19: R50.1 U2.57(TTL19)
TTL20: R47.1 U2.58(TTL20)
TTL21: R43.1 U2.59(TTL21)
TTL22: R44.1 U2.60(TTL22)
TTL23: R45.1 U2.61(TTL23)
TTL24/LCD_PCLK: R72.1 U2.62(TTL24)
TTL25/LCD_HSYNC: R67.1 U2.63(TTL25)
TTL26/LCD_VSYNC: R68.1 U2.64(TTL26)
TTL27/LCD_DE: R69.1 U2.65(TTL27)
UART0_RX: D30.A J11.2 R89.2
UART0_RX_: D29.1(I/O2) J10.3 J11.6
UART0_TX: J11.1 R88.1
UART0_TX_: D28.1(I/O2) J10.4 J11.5
UART1_RX: J12.18 U2.29(UART1_RX)
UART1_TX: J12.16 U2.30(UART1_TX)
UD+: D2.1(I/O2) J1.3(D+) U6.1(UD+)
UD-: D1.1(I/O2) J1.2(D-) U6.2(UD-)
USB-DRVVBUS: R19.2 R123.1 U3.4(EN)
USB_VBUS: C18.2 D16.1(I/O2) J5.1(VBUS) U3.1(VOUT)
WIFI_ANT: C11.2 R6.1 U2.3(WF_ANT)
WIFI_ANT_: C12.2 D6.1(I/O2) J3.2(SIG) R6.2
N992055: C13.2 J4.4(VDD) L3.2
N1029238: L1.1 U1.3(SW)
N1029242: C4.1 R3.2 R5.1 U1.5(FB)
N1030799: C16.1 Q1.1(GATE) R20.2 R21.2
N6892349: R22.1 U3.3(OCB)
N11463456: LED2.A(ANODE) R4.2
N11537825: C43.2 C44.2 R82.2 R83.1
N11641260: LED1.A(ANODE) R2.2
N11726744: J6.A4 J6.A5
N11726756: J6.A7 J6.A8
N11730332: C29.2 C30.2 R42.2
N11730936: R46.1 U5.25(ISET)
N11731046: C37.2 R53.2 R54.1 XT1.3
N11735014: R28.1 U4.21(MCT2)
N11735018: C23.2 R28.2
N11735022: C21.2 R24.2
N11735030: R24.1 U4.24(MCT1)
N11735054: R32.1 U4.18(MCT3)
N11735058: C25.2 R32.2
N11735062: C27.2 R35.2
N11735070: R35.1 U4.15(MCT4)
N11735786: C20.1 U4.1(TCT1)
N11735790: C22.1 U4.4(TCT2)
N11735890: C24.1 U4.7(TCT3)
N11735894: C26.1 U4.10(TCT4)
N11746324: J6.B4 J6.B5
N11746339: J6.B7 J6.B8
N11786183: C48.2 U6.10(V3)
N11786289: R88.2 U6.9(RXD)
N11786293: D30.C U6.8(TXD)
N11791074: R1.2 SW1.1
N11830519: J6.A10(ALEDY+) R36.1
N11830523: J6.A11(ALEDG-) R38.1

Pads without a net: J1 4; J10 1; J12 8 10 12 22 27 28; MARK1 1; MARK2 1; MARK3 1; MARK4 1; SW1 2 4; U5 1 6 7 15 16 24; U6 4 5 6

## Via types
v1: diameter 0.55, hole 0.3, TOP to BOTTOM, 674 vias

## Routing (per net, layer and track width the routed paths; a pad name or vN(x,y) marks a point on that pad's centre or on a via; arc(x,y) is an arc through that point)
GND: length 191.6
  TOP w0.203: v1(27.33,27.65) 32.15,22.82 v1(32.15,21.17) 32.15,19.14 30.63,17.61 28.6,17.61 v1(25.29,20.92)
  TOP w0.305: J7.28 49.87,29.61 50.57,28.92 52.22,28.92 52.45,29.15 v1(52.6,29.15) ; v1(51.84,31.15) 51.3,30.61 J7.26 ; J7.30 49.62,28.61 50.2,28.03 v1(50.31,28.03) ; 50.55,32.76 49.97,32.76 49.62,33.11 J7.21 ; C47.1 v1(3.96,66.95) ; v1(50.06,39.61) J7.8 ; J7.1 49.65,43.11 v1(49.93,43.4) ; J7.23 50.33,32.11 50.33,32.11 ; J7.2 v1(49.9,42.61) ; J7.32 49.62,27.61 50.09,27.14 51.2,27.14 v1(51.71,27.65)
  TOP w0.381: R58.1 48.53,48.86 v1(48.59,48.81)
  TOP w0.406: 4.69,79.82 v1(4.69,78.62)
  TOP w0.432: C35.1 37.29,49.62 37.14,49.77 v1(37.12,49.77)
  TOP w0.508: v1(45.21,23.22) 45.53,23.22 D24.2 ; D6.2 v1(7.39,45.3) ; C7.1 v1(17.61,46.32) ; C48.1 v1(7.18,67.35) ; C2.1 v1(22.77,9.61) ; U1.2 17.83,8.22 v1(17.31,8.74) 17.33,8.76 v1(17.33,9.61) ; v1(14.94,46.12) 14.49,46.12 C8.1 ; R22.2 v1(16.94,70.02) ; D2.2 v1(4.75,76.19) ; 29.9,6.69 29.9,5.76 30.25,5.42 R85.2 ; D14.2 v1(13.08,74.13) ; v1(14.87,46.82) 14.56,47.12 C10.1 ; U2.95 14.78,42.9 v1(14.38,42.51) ; C3.1 22.08,8.81 v1(22.08,9.29) ; C9.1 14.56,49.42 v1(13.9,50.08) ; C12.1 v1(7.51,44.16) ; v1(45.92,51.64) 45.92,52.92 R46.2 ; D26.2 v1(40.05,13.5) ; D25.2 v1(47.11,6.72) ; v1(45.21,26.5) 45.84,27.14 D22.2 D21.2 ; v1(38.43,52.67) 37.94,52.18 C36.1 ; v1(21.86,11.18) 21.35,11.69 R5.2 ; v1(36.22,45.37) 36.85,46 C37.1 ; C38.1 v1(42.44,30.7) ; XT1.2 v1(33.84,48.09) ; v1(25.13,41.77) v1(25.13,42.6) 25.78,43.24 U2.85 ; v1(39.64,35.14) 39.95,35.44 U2.66 ; U2.90 v1(20.28,42.86) ; 38.63,6.69 38.42,6.49 C44.1 ; v1(37.12,49.77) 35.94,49.77 XT1.4 ; U2.4 v1(10.36,38.74) ; U2.42 32.38,15.74 v1(32.15,15.96) ; R123.2 v1(16.94,68.72) ; J2.2 v1(9.8,60.94) ; U2.2 v1(10.36,40.94)
  TOP w0.711: 4.85,55.79 4.85,56.73 ; 4.85,56.73 4.85,57.67 ; 4.85,56.73 3.91,56.73 ; 4.85,56.73 5.79,56.73 ; 1.37,23.71 J12.14 ; J12.14 2.31,24.65 ; J12.14 2.31,22.77 ; J12.25 4.85,39.89 ; J12.25 3.91,38.95 ; J12.25 5.79,38.95 ; 1.37,49.11 2.31,49.11 ; 2.31,49.11 3.25,49.11 ; 2.31,49.11 2.31,50.05 ; 2.31,49.11 2.31,48.17 ; 34.69,73.38 J6.B11 35.58,72.49 ; 1.37,44.03 2.31,44.03 ; 2.31,44.03 3.25,44.03 ; 2.31,44.03 2.31,43.09 ; 2.31,44.03 2.31,44.97 ; 1.37,13.55 J12.6 ; J12.6 3.25,13.55 ; J12.6 2.31,14.49 ; J12.6 2.31,12.61 ; 4.85,17.69 J12.9 3.91,18.63 ; J6.B9 23.26,73.38 ; J6.B9 23.26,71.6 ; J6.B9 24.15,72.49 ; J6.B9 22.37,72.49 ; 39.01,71.6 J6.A9 ; J6.A9 39.9,72.49 ; J6.A9 39.01,73.38 ; J12.20 2.31,32.27 ; J12.20 3.25,31.33 ; J12.20 1.37,31.33 ; J12.20 2.31,30.39
  BOTTOM w0.203: v1(13.77,57.11) v1(6.62,57.11) ; v1(13.9,50.08) 13.9,47.78 v1(14.87,46.82) 14.87,46.19 v1(14.94,46.12) 14.94,43.07 v1(14.38,42.51) ; v1(17.61,46.32) 17.52,46.4 17.52,47.9
  BOTTOM w0.381: D8.2 D7.2 v1(36.32,42.38) ; D13.2 v1(36.32,40.98) ; C14.1 v1(33.95,41.11)
  BOTTOM w0.508: v1(45.21,23.22) 45.37,23.22 45.96,23.82 45.96,25.76 45.22,26.5 v1(45.21,26.5) ; J10.2 22.12,3.01 ; J10.2 20.34,3.01 ; J10.2 21.23,1.74 ; 41.42,49.62 v1(42.31,49.62) U5.33 v1(44.34,49.62) 45.49,49.62 ; D10.2 v1(36.32,36.16) ; v1(42.31,50.63) 41.3,50.63 ; v1(39.79,30.67) 40.17,31.05 J4.11 ; C17.1 25.48,38.38 25.13,38.73 v1(25.13,41.77) ; v1(44.34,50.63) 45.23,50.63 ; v1(44.34,48.86) 45.36,48.86 ; C13.1 36.08,39.33 v1(36.01,39.4) ; D9.2 v1(36.22,34.63) ; v1(36.22,45.37) 36.54,45.05 D12.2 ; v1(42.31,48.86) 41.42,48.86
  BOTTOM w0.711: 3.91,38.95 J12.25 4.85,38.01 ; J12.14 3.25,23.71 ; J12.14 1.37,23.71 ; J12.14 2.31,24.65 ; J12.14 2.31,22.77 ; J12.6 3.25,13.55 ; J12.6 1.37,13.55 ; J12.6 2.31,14.49 ; J6.B11 35.58,72.49 ; J6.B11 34.69,73.38 ; J6.B11 33.8,72.49 ; J6.B11 34.69,71.6 ; 12.35,76.99 J5.4 13.16,76.18 ; J12.20 2.31,32.27 ; J12.20 3.25,31.33 ; J12.20 2.31,30.39 ; J12.20 1.37,31.33 ; J6.B9 24.15,72.49 ; J6.B9 22.37,72.49 ; J6.B9 23.26,73.38 ; J6.B9 23.26,71.6 ; 2.31,48.17 2.31,49.11 ; 2.31,49.11 2.31,50.05 ; 2.31,49.11 1.37,49.11 ; 4.85,17.69 J12.9 ; J12.9 4.85,19.57 ; J12.9 3.91,18.63 ; 1.37,44.03 2.31,44.03 ; 2.31,44.03 2.31,43.09 ; 2.31,44.03 2.31,44.97
  vias: v1(0.91,57.62) v1(0.91,55.46) v1(0.91,53.56) v1(0.91,26.63) v1(0.91,24.98) v1(0.91,22.44) v1(0.91,19.9) v1(0.91,17.36) v1(0.91,14.82) v1(0.91,12.41) v1(0.91,9.61) v1(1.04,7.2) v1(1.93,47.84) v1(1.93,45.3) v1(1.93,42.76) v1(1.93,37.68) v1(1.93,35.14) v1(1.93,32.47) v1(1.93,30.06) v1(1.93,19.9) v1(1.93,17.36) v1(2.05,40.22) v1(2.05,22.44) v1(2.05,14.82) v1(2.18,50.38) v1(2.31,24.98) v1(2.81,66) v1(3.32,73.11) v1(3.58,38.7) v1(3.58,35.14) v1(3.58,33.11) v1(3.58,30.82) v1(3.58,29.81) v1(3.96,78.19) v1(4.08,73.11) v1(4.21,75.55) v1(4.59,77.81) v1(4.59,77.05) v1(5.35,78.07) v1(5.99,36.03) v1(6.12,64.73) v1(6.24,54.19) v1(6.37,52.03) v1(6.37,33.62) v1(6.37,6.18) v1(6.62,69.86) v1(6.62,50) v1(6.62,49.24) v1(6.62,48.48) v1(6.62,47.71) v1(6.62,46.95) v1(6.62,46.19) v1(6.88,5.55) v1(7.13,75.4) v1(7.13,74.51) v1(7.39,29.17) v1(7.5,58.64) v1(7.51,54.19) v1(7.51,30.7) v1(7.64,63.46) v1(7.64,62.19) v1(7.64,52.03) v1(7.64,50.76) v1(7.64,46.95) v1(7.64,46.19) v1(7.64,5.04) v1(7.64,3.77) v1(7.64,2.5) v1(7.64,1.23) v1(7.77,68.29) v1(7.77,28.16) v1(7.77,27.01) v1(8.02,31.97) v1(8.15,43.4) v1(8.15,42.63) v1(8.15,41.87) v1(8.28,51.4) v1(8.53,40.22) v1(8.91,63.46) v1(8.91,62.19) v1(8.91,54.19) v1(8.91,52.03) v1(9.04,39.59) v1(9.55,51.4) v1(9.67,39.08) v1(9.8,29.3) v1(9.93,44.92) v1(9.93,44.03) v1(9.93,43.01) v1(9.93,42) v1(10.05,30.57) v1(10.18,63.46) v1(10.18,62.19) v1(10.18,54.19) v1(10.18,52.03) v1(10.18,50.76) v1(10.18,46.06) v1(10.31,46.95) v1(11.2,46.95) v1(11.45,62.19) v1(11.45,54.19) v1(11.45,52.03) v1(11.45,50.76) v1(11.45,50) v1(11.45,49.24) v1(11.45,48.48) v1(11.45,47.71) v1(12.09,11.17) v1(12.59,72.86) v1(12.59,71.21) v1(12.72,62.19) v1(12.72,60.92) v1(12.72,59.65) v1(12.72,58.38) v1(12.72,54.19) v1(12.72,52.29) v1(12.85,44.54) v1(12.85,43.14) v1(12.87,31.08) v1(12.97,35.39) v1(12.97,34.63) v1(12.97,11.17) v1(13.23,19.65) v1(13.36,42.25) v1(13.36,40.98) v1(13.36,39.59) v1(13.86,52.29) v1(13.86,11.17) v1(13.99,60.92) v1(14.37,75.4) v1(14.37,71.21) v1(14.37,69.3) v1(14.75,11.17) v1(15.01,19.77) v1(15.26,59.65) v1(15.26,58.38) v1(15.26,57.11) v1(15.39,55.84) v1(15.39,31.08) v1(15.9,19.77) v1(16.02,34.25) v1(16.15,75.4) v1(16.15,54.83) v1(16.66,23.71) v1(16.91,73.24) v1(16.91,72.48) v1(16.91,71.72) v1(16.91,19.77) v1(17.55,74.13) v1(17.55,42.63) v1(17.67,69.43) v1(18.31,61.3) v1(18.31,60.41) v1(18.31,59.52) v1(18.31,58.64) v1(18.31,9.99) v1(18.56,71.84) v1(18.56,69.43) v1(18.56,57.62) v1(19.07,57.11) v1(19.08,36.41) v1(19.2,9.99) v1(19.32,8.22) v1(19.58,69.43) v1(20.1,55.17) v1(20.21,45.49) v1(20.21,41.74) v1(20.21,40.22) v1(20.21,9.99) v1(20.47,47.71) v1(20.59,69.43) v1(21.61,69.43) v1(21.74,61.18) v1(22.25,58.13) v1(22.25,17.61) v1(22.88,74.89) v1(22.88,73.62) v1(22.88,71.08) v1(22.88,69.81) v1(22.88,36.41) v1(22.88,35.39) v1(22.88,34.25) v1(22.88,33.11) v1(22.88,31.84) v1(23.01,59.91) v1(23.01,54.57) v1(23.39,23.84) v1(23.56,51.27) v1(23.9,20.92) v1(24.02,57.11) v1(24.02,55.59) v1(24.02,54.91) v1(24.15,73.62) v1(24.15,71.08) v1(24.15,69.81) v1(24.15,68.54) v1(24.15,67.27) v1(24.15,16.09) v1(24.28,17.74) v1(24.53,8.09) v1(24.91,16.09) v1(25.17,51.4) v1(25.42,78.7) v1(25.42,71.08) v1(25.42,69.81) v1(25.42,68.54) v1(25.42,67.27) v1(25.42,24.6) v1(25.55,17.74) v1(25.67,16.09) v1(26.56,64.73) v1(26.69,67.27) v1(27.07,26.5) v1(27.45,63.59) v1(27.83,8.72) v1(27.96,81.24) v1(27.96,1.23) v1(28.85,50.89) v1(28.85,49.24) v1(28.85,21.04) v1(29.23,60.92) v1(29.23,59.65) v1(29.23,58.38) v1(29.23,57.11) v1(29.23,55.84) v1(29.23,54.57) v1(29.74,32.35) v1(29.99,21.17) v1(29.99,20.03) v1(30.12,16.09) v1(30.12,12.79) v1(30.12,10.38) v1(30.25,30.06) v1(30.5,81.24) v1(30.5,67.27) v1(30.5,3.77) v1(30.5,1.23) v1(30.63,51.02) v1(30.75,30.57) v1(30.88,31.33) v1(30.88,23.33) v1(31.14,47.97) v1(31.14,47.21) v1(31.26,51.52) v1(31.64,55.59) v1(32.15,16.85) v1(32.41,54.95) v1(32.91,48.09) v1(33.04,81.24) v1(33.04,76.16) v1(33.04,73.62) v1(33.04,60.92) v1(33.04,1.23) v1(35.33,54.95) v1(35.33,54.19) v1(35.53,10.25) v1(35.58,81.24) v1(35.58,78.7) v1(35.58,76.16) v1(35.58,73.62) v1(35.58,63.46) v1(35.58,60.92) v1(35.58,10.92) v1(35.58,3.77) v1(35.58,1.23) v1(37.36,70.83) v1(38.12,81.24) v1(38.12,78.7) v1(38.12,76.16) v1(38.12,73.62) v1(38.12,63.46) v1(38.12,60.92) v1(38.12,18.38) v1(38.12,3.77) v1(38.12,1.23) v1(38.37,20.28) v1(38.65,41.74) v1(39.14,12.66) v1(39.39,20.28) v1(39.39,19.01) v1(39.39,17.74) v1(39.39,16.47) v1(39.36,10.4) v1(39.52,56.6) v1(39.52,55.84) v1(39.64,42.89) v1(39.64,40.86) v1(39.9,15.71) v1(40.15,14.95) v1(40.15,14.19) v1(40.41,71.46) v1(40.66,81.24) v1(40.66,78.7) v1(40.66,76.16) v1(40.66,73.62) v1(40.66,63.46) v1(40.66,62.19) v1(40.66,60.92) v1(41.93,63.46) v1(41.93,62.19) v1(41.93,60.92) v1(42.57,16.34) v1(42.55,15.22) v1(42.82,40.6) v1(43.2,81.24) v1(43.2,63.46) v1(43.2,62.19) v1(43.2,60.92) v1(43.2,39.84) v1(43.2,1.23) v1(43.33,50.63) v1(43.33,48.86) v1(43.84,40.35) v1(43.96,3.14) v1(44.47,59.65) v1(44.47,58.38) v1(44.47,57.11) v1(44.6,44.41) v1(44.85,14.57) v1(45.36,56.98) v1(45.61,41.74) v1(45.74,81.24) v1(45.74,58.38) v1(45.74,5.04) v1(45.74,2.5) v1(46,44.03) v1(46.12,57.75) v1(46.19,20.08) v1(46.38,17.74) v1(47.01,81.24) v1(47.01,73.62) v1(47.01,71.08) v1(48.28,6.31) v1(48.28,5.04) v1(48.28,3.77) v1(48.28,2.5) v1(48.28,1.23) v1(49.04,18.5) v1(49.17,44.54) v1(49.17,43.78) v1(49.55,76.16) v1(49.55,73.62) v1(49.55,71.08) v1(49.55,7.58) v1(49.55,6.31) v1(49.68,58.64) v1(50.69,57.62) v1(50.82,77.43) v1(50.82,7.58) v1(50.93,38.39) v1(51.24,36.12) v1(51.63,37.17) v1(51.84,53.68) v1(51.84,52.92) v1(51.94,10.38) v1(51.94,9.36) v1(52.09,76.16) v1(52.09,74.89) v1(52.09,73.62) v1(52.09,11.39) v1(52.22,57.62) v1(52.22,41.62) v1(52.6,53.68) v1(52.6,52.92) v1(52.6,52.16) v1(52.73,46.82) v1(52.72,31.15) v1(53.36,74.89) v1(53.36,73.62) v1(53.36,71.08) v1(53.36,57.11) v1(54.63,57.11) v1(54.63,55.84) v1(54.63,26.63) v1(54.63,24.09) v1(54.63,21.55) v1(54.63,13.93) v1(54.63,11.39) v1(54.76,9.36) v1(54.88,19.01) v1(55.01,54.83) v1(55.01,50.76) v1(55.01,46.57) v1(55.01,41.74) v1(55.01,38.44) v1(55.01,32.85) v1(55.01,29.68) v1(55.01,16.73)
GND_EARTH: length 53.4
  TOP w0.711: 21.92,79.46 J6.FG2 20.52,78.06 ; 2.36,81.65 J1.7 ; J1.7 1.55,82.92 ; J1.7 3.18,82.92 ; 11.66,79.59 J5.6 ; J5.6 13.46,79.59 ; J5.6 12.56,81.09 ; J5.5 18.86,79.59 ; J5.5 17.96,81.09 ; J5.5 17.06,79.59 ; 15.26,81.49 J5.7 ; J5.7 13.76,82.59 ; J5.7 15.26,83.69 ; J5.7 16.76,82.59 ; 3.56,80.99 J1.8 2.81,80.24 ; 9.61,81.65 J1.6 ; J1.6 8.8,82.92 ; J1.6 10.43,82.92 ; 9.17,80.24 J1.9 8.41,80.99
  BOTTOM w0.711: J5.7 16.76,82.59 ; J5.7 13.76,82.59 ; J5.7 15.26,81.49 ; J5.7 15.26,83.69 ; 3.56,80.99 J1.8 2.81,80.24 ; J1.7 3.18,82.92 ; J1.7 2.36,81.65 ; J1.7 1.55,82.92 ; 21.92,79.46 J6.FG2 23.31,78.06 ; J1.6 10.43,82.92 ; J1.6 9.61,81.65 ; J1.6 8.8,82.92 ; 8.41,80.99 J1.9 9.17,80.24 ; J5.5 18.86,79.59 ; J5.5 17.06,79.59 ; J5.5 17.96,81.09 ; J5.6 12.56,81.09 ; J5.6 13.46,79.59 ; J5.6 11.66,79.59 ; 49.22,61.56 H2.1 52.47,64.81
VCC5V: length 20.3
  TOP w0.254: 20.09,7.71 20.09,8.98 19.9,9.17 U1.1
  TOP w0.305: v1(8.4,72.73) 7.26,71.59 3.32,71.59 2.69,70.95 C47.2 3.35,68.35 3.71,68.71 U6.7
  BOTTOM w0.711: 2.31,10.07 J12.4 ; J12.4 3.25,11.01 ; J12.4 2.31,11.95 ; 2.31,7.53 J12.2 ; J12.2 3.25,8.47 ; J12.2 2.31,9.41
  vias: v1(8.4,74.51) v1(8.4,73.62) v1(11.58,74.51) v1(11.58,73.62) v1(11.58,72.73) v1(20.47,67.14) v1(20.47,66.38) v1(20.47,5.3) v1(21.23,67.14) v1(21.23,66.38) v1(21.23,5.3) v1(21.99,5.3) v1(52.22,23.58) v1(52.98,23.58)
VCC_RTC: length 7.1
  TOP w0.508: D5.C D4.C 15.71,47.59 16.1,47.19 C7.2 16.1,46.01 15.47,45.39 14.08,45.39 13.68,44.99 U2.96
50MHZ_CLKOUT: length 5.7
  TOP w0.203: U5.10 42.33,46.86 v1(42.2,46.73) ; U5.14 43.93,47.2 44.33,46.8 v1(44.45,46.8) 45.34,46.8 R52.2
  BOTTOM w0.203: v1(44.45,46.8) 42.27,46.8 v1(42.2,46.73)
AUD_LINEOUT_L0: length 52.5
  TOP w0.305: R80.1 40.96,9.51 40.47,9.02 39.73,9.02 39.36,9.39 32,9.39 31.29,10.1 31.29,11.24 v1(31.44,11.39) ; U2.92 18.08,43.42 18.37,43.13 18.37,40.2 21.69,36.89 21.69,31.25 25.93,27.01 25.93,25.11 29.1,21.94 30.89,21.94 31.44,22.48 v1(31.44,22.57)
  BOTTOM w0.305: v1(31.44,11.39) 31.29,11.54 31.29,22.42 v1(31.44,22.57)
AUD_LINEOUT_R0: length 53.5
  TOP w0.305: U2.91 19.18,43.43 18.88,43.13 18.88,40.41 22.19,37.1 22.19,31.46 26.44,27.22 26.44,25.32 29.31,22.44 30.51,22.44 v1(30.63,22.57) ; R81.1 42.06,8.52 39.52,8.52 39.15,8.88 31.74,8.88 30.78,9.84 30.78,11.24 v1(30.63,11.39)
  BOTTOM w0.305: v1(30.63,22.57) 30.78,22.42 30.78,11.54 v1(30.63,11.39)
AUD_MIC+: length 6.9
  TOP w0.305: R83.2 C45.1 R84.1 33.77,6.64 D27.2 33.77,2.85 J9.1
AUD_MIC-: length 7
  TOP w0.305: C46.1 R84.2 32.81,6.64 D27.1 R85.1 31.57,2.58 31.77,2.37
AUD_MICCM0: length 45.2
  TOP w0.305: U2.93 16.98,43.44 16.68,43.14 16.68,40.48 20.67,36.49 20.67,30.7 24.66,26.71 24.66,23.96 29.53,19.1 29.93,19.1 v1(30.07,19.25) ; v1(28.82,12.01) 28.99,11.84 28.99,8.84 30.71,7.12 C46.2
  BOTTOM w0.305: v1(28.82,12.01) 28.97,12.16 28.97,18.62 29.44,19.1 29.93,19.1 v1(30.07,19.25)
AUD_MICIN0: length 46
  TOP w0.305: C45.2 30.75,7.84 29.5,9.09 29.5,11.89 v1(29.62,12.01) ; U2.94 15.88,43.44 16.17,43.14 16.17,40.27 20.16,36.28 20.16,30.49 24.15,26.5 24.15,23.75 29.31,18.59 29.93,18.59 v1(30.07,18.44)
  BOTTOM w0.305: v1(30.07,18.44) 29.93,18.59 29.65,18.59 29.47,18.41 29.47,12.16 v1(29.62,12.01)
CRS: length 4.4
  TOP w0.203: R56.2 48.92,49.42 U5.20
DM_P2: length 32.5
  TOP w0.203: v1(19.63,55.76) 19.85,55.98 20.14,55.98 20.52,56.37 20.52,57.18 19.32,58.38 19.32,62.32 15.44,66.2 15.44,71.72 R12.1 ; U2.89 21.38,44.79 21.75,45.16 21.75,46.83 v1(21.53,47.06)
  BOTTOM w0.203: v1(21.53,47.06) 21.75,47.28 21.75,54.34 20.1,55.98 19.85,55.98 v1(19.63,55.76)
DM_P2_: length 4.7
  TOP w0.203: R12.2 15.44,73.24 15.44,73.77 D15.1 15.44,74.49 15.44,76.47 J5.2
DMIC_CLK: length 58.4
  TOP w0.203: U2.20 12.52,21.14 13.25,20.41 17.04,20.41 18.56,21.93 18.56,24.51 15.19,27.89 15.19,28.96 14.74,29.41 14.74,33.42 15.19,33.87 v1(15.19,34.36)
  BOTTOM w0.203: 2.31,56.73 3.27,57.7 5.25,57.7 6.52,56.43 13.49,56.43 15.73,54.18 15.73,48.54 16.91,47.36 16.91,42.44 15.97,41.49 15.97,35.15 v1(15.19,34.36)
DMIC_L: length 56.3
  TOP w0.203: v1(14.58,34.85) 14.58,34.84 14.58,34.12 14.08,33.63 14.08,29.2 14.58,28.71 14.58,27.64 17.93,24.28 17.93,22.31 16.66,21.04 13.48,21.04 12.28,22.24 U2.19
  BOTTOM w0.203: 2.31,54.19 3.88,55.77 6.83,55.77 6.88,55.82 13.24,55.82 15.12,53.93 15.12,48.29 16.3,47.1 16.3,42.69 15.36,41.75 15.36,35.63 v1(14.58,34.85)
DMIC_R: length 56
  TOP w0.203: U2.18 12.05,23.34 13.71,21.68 16.28,21.68 17.32,22.72 17.32,24.03 13.97,27.38 13.97,28.43 13.48,28.92 13.48,33.92 v1(13.97,34.41)
  BOTTOM w0.203: 2.31,51.65 3.58,52.92 3.58,54.44 4.34,55.21 12.98,55.21 14.51,53.68 14.51,48.03 15.7,46.85 15.7,42.94 14.75,42 14.75,35.9 13.97,35.12 v1(13.97,34.41)
DP_P2: length 32.5
  TOP w0.203: v1(19.63,56.56) 19.85,56.34 19.99,56.34 20.16,56.51 20.16,57.04 18.97,58.23 18.97,62.17 15.08,66.06 15.08,71.72 R14.1 ; v1(22.33,47.06) 22.1,46.83 22.1,45.16 22.48,44.79 U2.88
  BOTTOM w0.203: v1(19.63,56.56) 19.85,56.34 20.25,56.34 22.1,54.49 22.1,47.28 v1(22.33,47.06)
DP_P2_: length 4.7
  TOP w0.203: R14.2 15.08,73.24 15.08,73.77 D14.1 15.08,74.49 15.08,76.47 J5.3
ET_RX_ER-E: length 1.8
  TOP w0.203: R59.2 46.73,50 46.57,49.84 45.35,49.84 U5.21
ETH_RN: length 16.4
  TOP w0.203: U2.81 30.18,44.79 29.79,45.17 29.79,51.2 30.75,52.16 34.08,52.16 35.1,53.17 36.62,53.17 37.05,53.61 37.05,54.06 37.13,54.14 R27.1
ETH_RP: length 16.5
  TOP w0.203: U2.82 29.08,44.77 29.46,45.15 29.46,51.33 30.62,52.49 33.94,52.49 34.96,53.5 36.48,53.5 36.72,53.74 36.72,54.06 36.65,54.14 R26.1
ETH_RXN: length 4.5
  TOP w0.203: R27.2 37.02,55.47 37.02,55.75 37.33,56.07 D18.2 37.33,56.25 37.02,56.57 37.02,57.91 37.37,58.26 U4.6
ETH_RXP: length 4.5
  TOP w0.203: U4.5 36.37,58.23 36.68,57.91 36.68,56.57 36.37,56.25 D18.1 36.37,56.07 36.68,55.75 36.68,55.47 R26.2
ETH_TN: length 15.1
  TOP w0.203: R25.1 34.28,54.14 34.04,53.91 34.04,53.59 33.65,53.2 30.23,53.2 27.59,50.56 27.59,45.16 27.98,44.78 U2.83
ETH_TP: length 15.2
  TOP w0.203: U2.84 26.88,44.75 27.26,45.14 27.26,50.7 30.09,53.53 33.51,53.53 33.71,53.73 33.71,53.91 33.48,54.14 R23.1
ETH_TXN: length 4.4
  TOP w0.203: U4.3 34.37,58.31 34.03,57.98 34.03,56.47 D17.2 34.28,56.19 33.97,55.88 33.97,55.47 R25.2
ETH_TXP: length 4.5
  TOP w0.203: U4.2 33.37,58.31 33.7,57.97 33.7,56.6 D17.1 33.32,56.19 33.64,55.88 33.64,55.47 R23.2
ETH_XI: length 8.9
  TOP w0.203: XT1.1 34.86,48.35 36.02,48.35 36.7,49.03 R53.1 36.89,49.07 38.3,49.07 38.8,49.57 C35.2 38.8,49.64 39.79,50.62 40.8,50.62 40.8,50.62 U5.2
ETH_XO: length 3.6
  TOP w0.203: U5.3 39.98,50.22 39.33,49.57 39.33,49.23 38.8,48.71 R54.2
FUART_CTS: length 46.9
  TOP w0.203: U2.33 22.48,15.66 21.14,17.01 21.14,25.67 17.65,29.16 17.65,34.62 15.03,37.24 v1(13.6,37.24)
  BOTTOM w0.203: 4.85,49.11 3.83,48.09 3.83,45.94 4.47,45.3 4.97,45.3 5.81,44.46 5.81,43.2 6.76,42.25 6.76,41.15 7.03,40.88 7.03,39.43 9.89,36.58 13.07,36.58 13.6,37.1 v1(13.6,37.24)
FUART_RTS: length 48
  TOP w0.203: U2.34 23.58,15.14 21.54,17.17 21.54,25.84 18.05,29.33 18.05,34.79 14.85,37.99 v1(13.46,37.99)
  BOTTOM w0.203: 4.85,51.65 4.85,51.14 5.89,50.1 5.89,45.54 6.62,44.8 6.62,43.54 7.57,42.59 7.57,41.49 7.84,41.22 7.84,39.89 10,37.74 13.21,37.74 v1(13.46,37.99)
FUART_RX: length 41
  TOP w0.203: U2.31 20.28,16.28 20.32,16.33 20.32,25.34 16.83,28.82 16.83,34.28 15.22,35.9 13.56,35.9 12.83,36.63 v1(12.83,37.16)
  BOTTOM w0.203: 4.85,46.57 4.85,46 6.22,44.63 6.22,43.37 7.16,42.42 7.16,41.32 7.44,41.05 7.44,39.66 9.94,37.16 v1(12.83,37.16)
FUART_TX: length 39.9
  TOP w0.203: v1(13.8,36.48) 15.21,36.48 17.24,34.45 17.24,28.99 20.73,25.5 20.73,16.21 21.38,15.56 U2.32
  BOTTOM w0.203: v1(13.8,36.48) 13.49,36.17 9.66,36.17 6.62,39.2 6.62,40.71 6.35,40.99 6.35,42.09 4.85,43.59 4.85,44.03
GPIO0/RMII_MDIO: length 29.7
  TOP w0.203: U2.74 37.88,45.06 38.12,45.3 39.33,45.3 43.21,41.42 43.21,41.33 v1(43.42,41.12) ; v1(51.96,51.65) 50.06,51.65 48.28,53.43 R40.1
  BOTTOM w0.203: v1(43.42,41.12) 44.1,41.12 45.36,42.38 46.06,42.38 50.38,46.7 51.71,46.7 53.11,48.09 53.11,50.51 v1(51.96,51.65)
GPIO1/RMII_MDC: length 28.2
  TOP w0.203: R41.1 51.58,51.14 v1(51.96,50.76) ; v1(43.84,41.74) 43.45,41.74 39.52,45.68 37.61,45.68 36.78,44.85 U2.75
  BOTTOM w0.203: v1(43.84,41.74) 44.85,42.76 45.87,42.76 50.21,47.1 51.48,47.1 52.6,48.22 52.6,50.13 v1(51.96,50.76)
GPIO2/I2C1_SCL: length 44.2
  TOP w0.203: v1(42.4,20.34) 42.41,20.33 43.23,20.33 R77.1 ; v1(39.72,21.42) 39.21,21.93 34.73,21.93 25.54,31.12 25.54,34.95 25.42,35.07 25.42,40.51 26.12,41.2 26.12,42.06 26.7,42.64 34.7,42.64 35.68,43.62 U2.76
  BOTTOM w0.203: v1(39.72,21.42) 41.31,21.42 v1(42.4,20.34)
GPIO3/I2C1_SDA: length 44.7
  TOP w0.203: U2.77 34.58,43.41 34.22,43.05 26.53,43.05 25.71,42.23 25.71,41.37 25.02,40.68 25.02,34.9 25.14,34.78 25.14,30.95 34.73,21.35 38.83,21.35 v1(39.01,21.17) ; v1(42.37,22.22) 42.59,22.44 R76.1
  BOTTOM w0.203: v1(39.01,21.17) 39.01,21.58 39.64,22.22 v1(42.37,22.22)
GPIO4/PWM0: length 58.8
  TOP w0.203: v1(37.61,19.14) 33.29,19.14 31.14,16.98 23.91,16.98 21.95,18.94 21.95,26.01 18.46,29.5 18.46,34.96 14.85,38.57 13.1,38.57 12.17,37.64 U2.5 ; v1(42.37,25.57) 42.22,25.72 42.22,28.37 43.28,29.43 R70.1
  BOTTOM w0.203: v1(42.37,25.57) 40.3,25.57 40.02,25.29 38.62,25.29 37.35,24.02 37.35,23.33 37.61,23.08 v1(37.61,19.14)
GPIO5/PWM1: length 16.3
  TOP w0.203: v1(2.91,42.49) 3.35,42.49 3.78,42.91 5.4,42.91 6.22,42.09 6.22,40.88 10.56,36.54 U2.6
  BOTTOM w0.203: v1(2.91,42.49) 3.27,42.12 3.27,39.92 2.31,38.95
GPIO6/I2C0_SCL: length 25.8
  TOP w0.203: v1(9.55,34.51) 10.48,35.44 U2.7
  BOTTOM w0.203: v1(9.55,34.51) 8.66,34.51 5.99,31.84 5.99,14.69 J12.5
GPIO7/I2C0_SDA: length 27.5
  TOP w0.203: U2.8 10.65,34.34 v1(10.18,33.87)
  BOTTOM w0.203: J12.3 4.85,12.03 6.5,13.68 6.5,31.58 8.78,33.87 v1(10.18,33.87)
GPIO8/UART2_RX/SPI0_CZ: length 11.6
  TOP w0.203: 2.31,36.41 3.58,37.68 5.23,37.68 9.67,33.24 U2.9
GPIO9/UART2_TX/SPI0_CK: length 8.6
  TOP w0.203: J12.23 4.85,36.16 8.86,32.14 U2.10
GPIO10/SPI0_DI: length 7.9
  TOP w0.203: J12.21 7.37,31.35 10.29,31.35 10.6,31.04 U2.11
GPIO11/SPI0_DO: length 7.3
  TOP w0.203: U2.12 7,29.94 5.61,31.33 J12.19
GPIO12: length 68.6
  TOP w0.203: J12.11 4.85,21.04 6.37,19.52 6.37,15.07 8.6,12.84 v1(13.61,12.84) ; v1(31.13,29.46) 31.14,29.46 34.84,25.76 39.2,25.76 v1(39.31,25.87) ; R79.1 43.28,27.06 43.55,26.79 v1(43.55,26.63) ; U2.13 12.16,28.84 13.13,27.88 13.13,26.22 15.26,24.09 v1(15.77,24.09)
  BOTTOM w0.203: v1(13.61,12.84) 13.86,13.1 13.86,22.99 14.96,24.09 v1(15.77,24.09) 15.77,23.58 16.28,23.08 24.74,23.08 v1(31.13,29.46) ; v1(43.55,26.63) 43.07,26.15 40.3,26.15 40.02,25.87 v1(39.31,25.87)
GPIO13: length 67.2
  TOP w0.203: v1(14.75,12.15) 14.46,11.86 8.06,11.86 4.85,15.07 J12.7 ; v1(45.23,24.43) 45.65,24.43 R78.1 ; v1(39.79,23.76) 39.79,23.84 39.79,23.84 39.79,24.77 39.31,25.25 34.53,25.25 v1(31.13,28.64) ; v1(15.14,23.45) 15.14,23.35 15.12,23.33 15.08,23.33 12.72,25.69 12.72,27.27 12.25,27.74 U2.14
  BOTTOM w0.203: v1(39.79,23.76) 40.21,23.76 40.63,24.18 44.3,24.18 44.55,24.43 v1(45.23,24.43) ; v1(14.75,12.15) 14.37,12.53 14.37,22.68 v1(15.14,23.45) 15.14,23.45 15.92,22.67 25.16,22.67 v1(31.13,28.64)
GPIO14: length 1.7
  TOP w0.203: U2.15 10.57,26.64 10.39,26.46 R19.1
GPIO47: length 24.3
  TOP w0.203: J12.13 7.18,21.37 7.18,15.79 9.04,13.93 12.59,13.93 12.97,14.31 12.97,16.05 14.24,17.32 16.33,17.32 16.53,17.12 16.53,16.34 15.88,15.69 U2.27
GPIO48: length 26.6
  TOP w0.203: U2.28 16.98,17.24 16.5,17.72 14.07,17.72 12.57,16.22 12.57,14.54 12.36,14.34 9.27,14.34 7.64,15.96 7.64,22.57 4.85,25.36 J12.15
GPIO85: length 33.3
  TOP w0.203: LED1.C 19.16,48.37 v1(18.5,47.71) ; U2.16 9.95,25.54 8.41,27.08 v1(8.41,27.53)
  BOTTOM w0.203: v1(18.5,47.71) 18.19,47.4 18.19,42.27 16.91,41 16.91,33.11 16.15,32.35 10.31,32.35 8.41,30.45 v1(8.41,27.53)
GPIO86: length 38.2
  TOP w0.203: v1(42.8,26.73) 42.76,26.77 42.76,28.02 R71.1 ; v1(39.79,26.45) 34.96,26.45 v1(32.36,29.05) ; U2.17 12.62,24.44 14.63,22.44 v1(15.13,22.44)
  BOTTOM w0.203: v1(32.36,29.05) 25.5,22.19 15.39,22.19 v1(15.13,22.44) ; v1(39.79,26.45) 40.06,26.73 v1(42.8,26.73)
GPIO90: length 1.9
  TOP w0.203: U2.21 10.63,20.04 R21.1
INTN: length 3.5
  TOP w0.203: J7.34 47.6,26.61 D21.1 46.81,25.82 R78.2
LAN0-R+: length 15.5
  TOP w0.203: J6.B3 28.59,76.93 29.28,76.24 29.28,75.39 33.54,71.13 35.55,71.13 36.7,69.98 36.7,69.69 36.37,69.36 U4.20
LAN0-R-: length 15.4
  TOP w0.203: U4.19 37.37,69.36 37.03,69.69 37.03,70.12 35.68,71.46 33.68,71.46 29.61,75.53 29.61,76.03 29.87,76.29 31.63,76.29 31.77,76.43 31.77,77.18 J6.B6
LAN0-T+: length 14.6
  TOP w0.203: J6.B1 26.23,78.77 26.23,76.66 32.8,70.09 33.52,70.09 33.7,69.91 33.7,69.69 33.37,69.36 U4.23
LAN0-T-: length 14.7
  TOP w0.203: U4.22 34.37,69.36 34.03,69.69 34.03,70.05 33.66,70.42 32.94,70.42 26.56,76.8 26.56,77.72 26.89,78.05 27.18,78.05 27.57,77.66 J6.B2
LAN1-R+: length 12.3
  TOP w0.203: U4.14 42.37,69.36 42.7,69.69 42.7,70.03 45.23,72.56 45.23,76.03 44.34,76.93 J6.A3
LAN1-R-: length 12.4
  TOP w0.203: U4.13 43.37,69.36 43.03,69.69 43.03,69.9 45.56,72.43 45.56,76.03 45.82,76.29 47.66,76.29 47.88,76.51 47.88,76.82 J6.A6
LAN1-T+: length 13.7
  TOP w0.203: J6.A1 42.3,78.39 41.93,78.03 41.93,75.15 42.87,74.21 42.87,71.73 41.97,70.83 40.41,70.83 39.7,70.12 39.7,69.69 39.37,69.36 U4.17
LAN1-T-: length 13.9
  TOP w0.203: U4.16 40.37,69.36 40.03,69.69 40.03,69.98 40.55,70.5 42.11,70.5 43.2,71.59 43.2,74.34 42.26,75.28 42.26,77.89 42.44,78.07 42.73,78.07 43.32,77.47 J6.A2
